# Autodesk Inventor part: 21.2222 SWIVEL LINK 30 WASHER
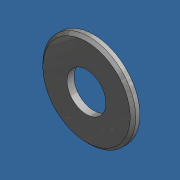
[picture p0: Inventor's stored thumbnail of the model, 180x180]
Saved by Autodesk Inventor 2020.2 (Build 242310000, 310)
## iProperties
Part Number: 21.2222 SWIVEL LINK 30 WASHER
Material: Generic
Document SubType Name: Modeling
Designer: amoles
Appearance: Default
Author: amoles
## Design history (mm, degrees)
feature "Base1"
body "Solid1"
